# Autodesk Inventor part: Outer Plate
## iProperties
Created: 2002-04
Part Number: Outer Plate
Document SubType Name: Modeling
Control State: 0
Master: False
Checked Out: False
PropertySet Name: Design Tracking Control
Shininess: 77.0
Angle Display Precision: 2
Document Length Units: 11269
Document Angle Units: 11283
Document Time Units: 11279
Document Mass Units: 11290
Document Length Units Precision: 3
Document Angle Units Precision: 2
Compacted: False
PropertySet Name: _Private Model Information
Density: 0.0
Volumn: 0.0
Area: 0.0
PropertySet Name: Model Information
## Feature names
1. Extrusion1
2. Extrusion2
